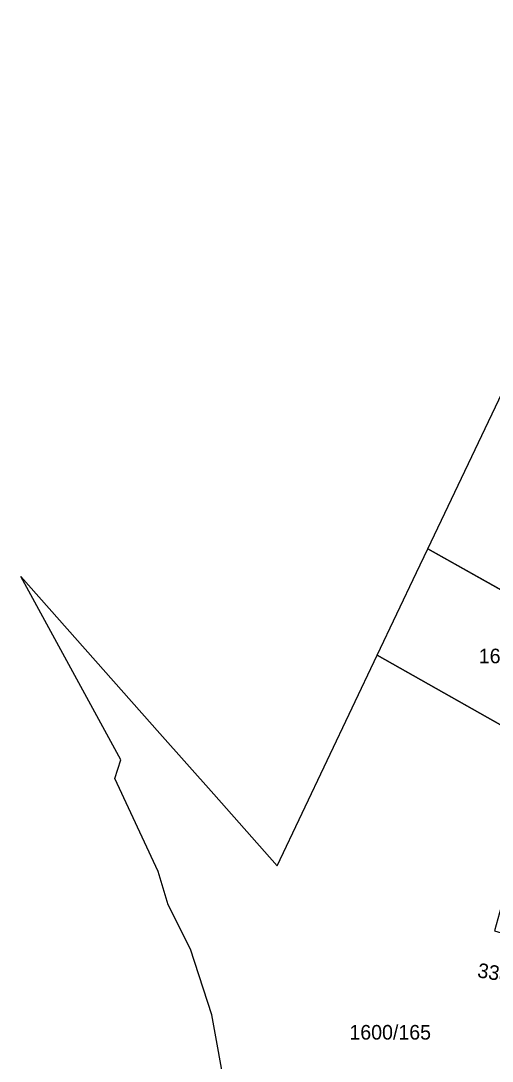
# Model space of a CAD drawing. Extents: x -262715 to -259381, y -1237238 to -1231182.
# Drawn here: x -261723 to -261658.5, y -1236858.1 to -1236715.8 of the extents above; entities that cross this region are included whole.
import ezdxf

# ---------------------------------------------------------------- set-up
doc = ezdxf.new("R2010")
doc.units = 0
for name, color, linetype in [('body_kn', 7, 'Continuous'), ('kladpar_druhypozemkov', 7, 'Continuous'), ('kladpar_hranice', 7, 'Continuous'), ('kladpar_parcelnecisla', 7, 'Continuous'), ('kladpar_plochy', 7, 'Continuous')]:
    doc.layers.add(name, color=color, linetype=linetype)

msp = doc.modelspace()

# ---------------------------------------------------------------- linework, layer by layer
at = {"layer": 'body_kn'}
for p, q in [((-261667.29, -1236787.99), (-261667.29, -1236787.99)), ((-261722.96, -1236791.79), (-261722.96, -1236791.79)), ((-261668.84, -1236791.25), (-261668.84, -1236791.25)), ((-261674.22, -1236802.56), (-261674.22, -1236802.56)), ((-261674.22, -1236802.56), (-261674.22, -1236802.56)), ((-261703.94, -1236813.25), (-261703.94, -1236813.25)), ((-261709.27, -1236816.87), (-261709.27, -1236816.87)), ((-261710.11, -1236819.42), (-261710.11, -1236819.42)), ((-261696.58, -1236821.56), (-261696.58, -1236821.56)), ((-261687.91, -1236831.35), (-261687.91, -1236831.35)), ((-261704.2, -1236832.13), (-261704.2, -1236832.13)), ((-261702.8, -1236836.71), (-261702.8, -1236836.71)), ((-261699.75, -1236842.76), (-261699.75, -1236842.76)), ((-261696.83, -1236851.75), (-261696.83, -1236851.75))]:
    msp.add_line(p, q, dxfattribs=at)
at = {"layer": 'kladpar_druhypozemkov'}
msp.add_line((-261672.69, -1236853.1), (-261672.69, -1236853.1), dxfattribs=at)
at = {"layer": 'kladpar_hranice'}
for p, q in [((-261667.29, -1236787.99), (-261634.96, -1236806.19)), ((-261634.96, -1236806.19), (-261667.29, -1236787.99)), ((-261639.89, -1236821.99), (-261674.22, -1236802.56)), ((-261674.22, -1236802.56), (-261639.89, -1236821.99))]:
    msp.add_line(p, q, dxfattribs=at)
for points in [[(-261667.29, -1236787.99), (-261622.98, -1236694.82), (-261628.21, -1236689.57)], [(-261674.22, -1236802.56), (-261668.84, -1236791.25), (-261667.29, -1236787.99)], [(-261694.88, -1236862.55), (-261696.83, -1236851.75), (-261699.75, -1236842.76), (-261702.8, -1236836.71), (-261704.2, -1236832.13), (-261710.11, -1236819.42), (-261709.27, -1236816.87), (-261722.96, -1236791.79), (-261703.94, -1236813.25), (-261696.58, -1236821.56), (-261687.91, -1236831.35), (-261674.22, -1236802.56)]]:
    msp.add_lwpolyline(points, dxfattribs=at)
at = {"layer": 'kladpar_plochy'}
for points in [[(-261634.96, -1236806.19), (-261667.29, -1236787.99), (-261622.98, -1236694.82), (-261628.21, -1236689.57), (-261616.27, -1236667.16), (-261616.32, -1236674.75), (-261619.69, -1236681.41), (-261616.37, -1236683.27), (-261616.42, -1236691.04), (-261616.66, -1236719.48), (-261617.01, -1236744.91), (-261617.53, -1236748.67), (-261621.67, -1236762.66), (-261624.31, -1236771.3), (-261627.23, -1236780.87), (-261630.43, -1236791.34)], [(-261674.22, -1236802.56), (-261668.84, -1236791.25), (-261667.29, -1236787.99), (-261634.96, -1236806.19), (-261638.01, -1236816.18), (-261639.89, -1236821.99)]]:
    msp.add_lwpolyline(points, close=True, dxfattribs=at)
msp.add_lwpolyline([(-261694.88, -1236862.55), (-261696.83, -1236851.75), (-261699.75, -1236842.76), (-261702.8, -1236836.71), (-261704.2, -1236832.13), (-261710.11, -1236819.42), (-261709.27, -1236816.87), (-261722.96, -1236791.79), (-261703.94, -1236813.25), (-261696.58, -1236821.56), (-261687.91, -1236831.35), (-261674.22, -1236802.56), (-261639.89, -1236821.99), (-261643.48, -1236833.08), (-261654.96, -1236828.19), (-261655.46, -1236830.41), (-261658.19, -1236840.26), (-261646.89, -1236843.62), (-261648.37, -1236848.2), (-261646.58, -1236849.55), (-261647.26, -1236851.41), (-261659.53, -1236884.95)], dxfattribs=at)

# ---------------------------------------------------------------- texts
at = {"layer": 'kladpar_parcelnecisla'}
for s, p in [('1600/164', (-261660.34, -1236803.66)), ('1600/165', (-261678.03, -1236855.14))]:
    msp.add_text(s, height=2, dxfattribs=at).set_placement(p)
msp.add_text('3388/37', height=2, rotation=351, dxfattribs=at).set_placement((-261660.62, -1236846.61))

doc.saveas('drawing.dxf')
